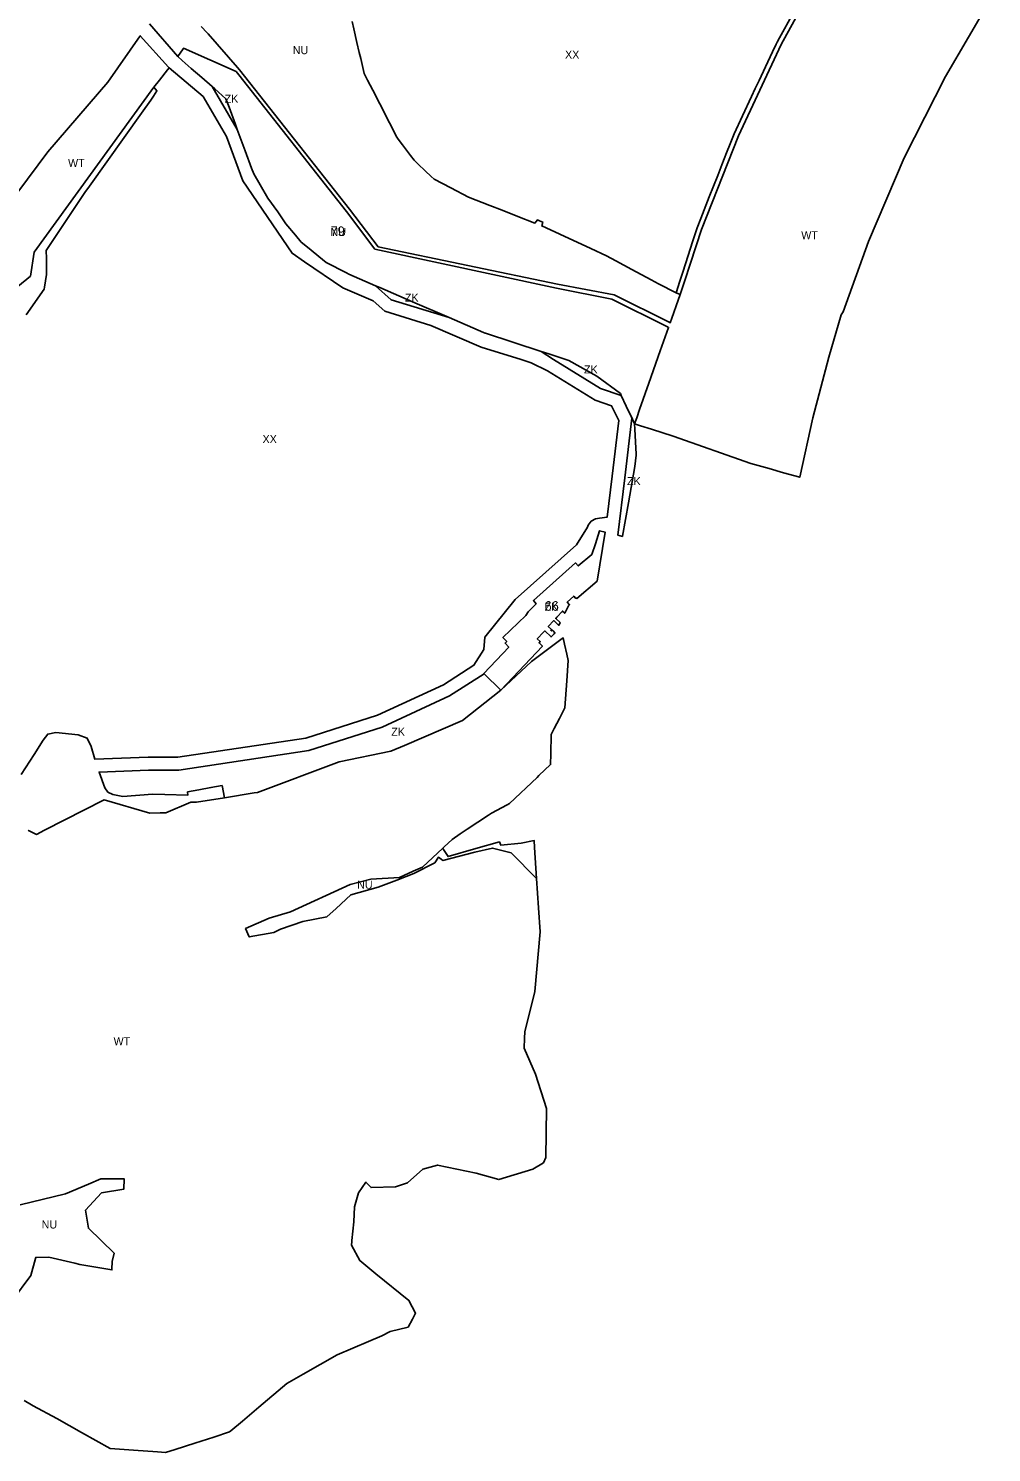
# Model space of a CAD drawing. Extents: x -537068 to -534056, y -1176840 to -1172401.
# Drawn here: x -535534 to -534932, y -1176840 to -1175951 of the extents above; entities that cross this region are included whole.
import ezdxf

# ---------------------------------------------------------------- set-up
doc = ezdxf.new("R2010")
doc.units = 0
for name, color, linetype in [('90550013', 7, 'Continuous'), ('90640013', 7, 'Continuous'), ('90710013', 7, 'Continuous'), ('90710023', 7, 'Continuous'), ('90730013', 7, 'Continuous'), ('90730023', 7, 'Continuous'), ('ID_navrh', 7, 'Continuous')]:
    doc.layers.add(name, color=color, linetype=linetype)

msp = doc.modelspace()

# ---------------------------------------------------------------- linework, layer by layer
at = {"layer": '90550013'}
for points in [[(-535055.84, -1175941.16), (-535064.33, -1175956.65), (-535065.83, -1175959.38), (-535066.01, -1175959.75), (-535066.44, -1175960.66), (-535068.64, -1175965.35), (-535073.02, -1175974.66), (-535077.11, -1175983.38), (-535079.45, -1175988.36), (-535081.8, -1175993.37), (-535087.42, -1176005.32), (-535092.73, -1176016.62), (-535095.2, -1176022.89), (-535097.4, -1176028.49), (-535100.38, -1176036.06), (-535102.94, -1176042.57), (-535105.58, -1176049.27), (-535108.19, -1176055.91), (-535113.55, -1176069.53), (-535115.85, -1176075.39), (-535118.68, -1176084.13), (-535121.45, -1176092.69), (-535124.8, -1176103.02), (-535126.61, -1176108.62), (-535128.98, -1176115.95), (-535139.88, -1176110.34), (-535144.42, -1176107.88), (-535156.56, -1176101.32), (-535166.59, -1176095.9), (-535172.35, -1176092.79), (-535182.15, -1176088.27), (-535201.51, -1176079.34), (-535210.2, -1176075.34), (-535212.9, -1176074.1), (-535212.25, -1176071.68), (-535214.34, -1176070.85), (-535215.59, -1176070.35), (-535217.14, -1176072.33), (-535227.84, -1176068.14), (-535237.65, -1176064.31), (-535245.33, -1176061.3), (-535258.67, -1176056.08), (-535269.7, -1176050.34), (-535280.18, -1176044.88), (-535281.9, -1176043.26), (-535285.76, -1176039.61), (-535290.15, -1176035.46), (-535292.63, -1176033.12), (-535294.94, -1176030.03), (-535299.8, -1176023.52), (-535302.51, -1176019.89), (-535303.44, -1176018.64), (-535304.61, -1176016.37), (-535306.6, -1176012.48), (-535309.37, -1176007.08), (-535311.4, -1176003.13), (-535314.15, -1175997.77), (-535318.46, -1175989.39), (-535321.72, -1175983.04), (-535323.82, -1175978.94), (-535325.11, -1175973.34), (-535326.01, -1175969.46), (-535326.87, -1175965.76), (-535328.33, -1175959.48), (-535330.29, -1175951), (-535331.33, -1175946.51)], [(-535534.97, -1176129.73), (-535523.9, -1176113.7), (-535523.65, -1176112.33), (-535522.26, -1176104.52), (-535522.4, -1176094.37), (-535522.46, -1176089.49), (-535498.36, -1176053.32), (-535495.52, -1176049.34), (-535462.94, -1176003.66), (-535457.15, -1175995.54), (-535455.51, -1175993.05), (-535453.36, -1175989.8), (-535455.23, -1175987.51), (-535451.76, -1175983.06), (-535446.65, -1175976.52), (-535445.68, -1175975.28), (-535424.54, -1175993.21), (-535409.82, -1176018.17), (-535399.63, -1176045.97), (-535368.9, -1176091.15), (-535361.09, -1176096.62), (-535337.12, -1176112.77), (-535318.31, -1176120.82), (-535310.89, -1176127.38), (-535282.17, -1176136.28), (-535250.78, -1176149.88), (-535225.72, -1176157.63), (-535219.59, -1176159.68), (-535209.28, -1176164.66), (-535179.48, -1176182.91), (-535169.19, -1176186.4), (-535164.8, -1176195.6), (-535168.88, -1176230.42), (-535172.06, -1176256.14), (-535176.74, -1176256.58), (-535179.27, -1176256.99), (-535181.94, -1176258.5), (-535183.88, -1176260.97), (-535184.38, -1176262.21), (-535191.15, -1176273.27), (-535229.41, -1176307.51), (-535248.48, -1176331.01), (-535249.03, -1176338.8), (-535255.23, -1176348.54), (-535274.29, -1176360.72), (-535315.47, -1176379.78), (-535360.25, -1176394.06), (-535440.34, -1176406), (-535458.72, -1176406), (-535492.23, -1176407.19), (-535494.36, -1176399.33), (-535496.85, -1176394.02), (-535502.56, -1176391.94), (-535516.43, -1176390.57), (-535521.55, -1176391.5), (-535524.51, -1176395.44), (-535530.06, -1176404.25), (-535538.13, -1176416.77)]]:
    msp.add_lwpolyline(points, dxfattribs=at)
at = {"layer": '90640013'}
for points in [[(-535425.64, -1175949.46), (-535421.93, -1175953.47), (-535421.33, -1175954.12), (-535402.94, -1175975.2), (-535401.83, -1175976.6), (-535332.94, -1176063.63), (-535315.13, -1176087.1), (-535203.12, -1176110.45), (-535167.7, -1176117.17), (-535133.32, -1176134.27), (-535132.61, -1176134.62), (-535131.63, -1176131.83), (-535127.65, -1176120.53), (-535126.42, -1176117.04), (-535123.51, -1176108.22), (-535112.98, -1176076.3), (-535089.97, -1176017.76), (-535063.2, -1175960.77), (-535033.24, -1175906.1)], [(-534931.82, -1175931.47), (-534960.54, -1175980.81), (-534986.37, -1176031.62), (-535008.76, -1176083.79), (-535024.61, -1176127.82), (-535025.82, -1176129.74), (-535033.52, -1176156.02), (-535043.53, -1176194.1), (-535051.68, -1176231.16), (-535061.71, -1176228.3), (-535070.7, -1176225.74), (-535082.15, -1176222.47), (-535130.73, -1176205.55), (-535144.25, -1176201.17), (-535151.07, -1176198.96), (-535154.82, -1176197.75), (-535153.49, -1176193.96), (-535151.7, -1176188.89), (-535145.91, -1176172.43), (-535138.79, -1176152.2), (-535133.61, -1176137.48), (-535134.66, -1176136.96), (-535169.04, -1176119.86), (-535203.59, -1176112.91), (-535317.12, -1176088.61), (-535334.93, -1176065.14), (-535402.23, -1175979.7), (-535403.85, -1175977.64), (-535436.69, -1175963.12), (-535436.86, -1175963.37), (-535437.02, -1175963.6), (-535440.26, -1175968.33), (-535457.98, -1175947.84)], [(-535533.71, -1176451.64), (-535533.49, -1176451.75), (-535528.65, -1176454.2), (-535523.63, -1176451.66), (-535486.24, -1176432.72), (-535457.69, -1176441.02), (-535451.28, -1176440.64), (-535447.75, -1176440.73), (-535432.24, -1176433.99), (-535428.71, -1176434.07), (-535411.14, -1176431.27), (-535392.59, -1176428.31), (-535390.42, -1176427.96), (-535339.41, -1176408.87), (-535307.24, -1176402.28), (-535298.7, -1176398.63), (-535262.36, -1176383.13), (-535238.41, -1176364.03), (-535219.26, -1176346.29), (-535200.88, -1176332.56), (-535199.44, -1176331.49), (-535198.61, -1176335.33), (-535197.26, -1176341.53), (-535196.38, -1176345.61), (-535197.28, -1176358.28), (-535198.48, -1176375.15), (-535201.88, -1176381.84), (-535205.08, -1176388.14), (-535206.96, -1176391.84), (-535207.19, -1176403.93), (-535207.32, -1176410.61), (-535214.63, -1176417.52), (-535215.74, -1176418.57), (-535232.97, -1176434.86), (-535234.57, -1176435.74), (-535244.18, -1176441.03), (-535246.07, -1176442.27), (-535259.38, -1176450.99), (-535263.89, -1176453.95), (-535268.77, -1176457.43), (-535273.76, -1176462.03), (-535274.65, -1176462.84), (-535287.44, -1176474.62), (-535293.14, -1176477.21), (-535301.82, -1176481.16), (-535319.57, -1176482.1), (-535332.49, -1176485.54), (-535369.95, -1176502.58), (-535383.1, -1176506.55), (-535397.91, -1176513.07), (-535395.69, -1176518.21), (-535380.34, -1176515.47), (-535376.22, -1176513.36), (-535362.19, -1176508.54), (-535347.18, -1176505.79), (-535341.33, -1176500.46), (-535332.11, -1176492.04), (-535315, -1176487.27), (-535303.38, -1176482.75), (-535292.89, -1176478.68), (-535279.66, -1176471.94), (-535277.47, -1176468.51), (-535275.78, -1176469.69), (-535274.71, -1176470.43), (-535254.68, -1176465.39), (-535243.6, -1176462.73), (-535231.98, -1176465.74), (-535216.08, -1176481.68), (-535214.91, -1176500.06), (-535213.95, -1176515.16), (-535217.22, -1176552.4), (-535223.43, -1176577.55), (-535223.63, -1176581.58), (-535223.93, -1176587.8), (-535216.72, -1176603.99), (-535209.82, -1176625.43), (-535210.4, -1176656.13), (-535211.81, -1176659.3), (-535218.36, -1176663.32), (-535239.7, -1176669.83), (-535253.79, -1176665.86), (-535277.94, -1176660.78), (-535287.21, -1176663.4), (-535296.79, -1176671.9), (-535304.16, -1176674.29), (-535319.53, -1176674.86), (-535322.75, -1176671.4), (-535327.36, -1176678.19), (-535329.8, -1176686.93), (-535330.38, -1176696.29), (-535331.55, -1176707.87), (-535331.62, -1176708.58), (-535331.85, -1176710.83), (-535326.51, -1176720.46), (-535316.52, -1176728.73), (-535295.86, -1176745.33), (-535291.71, -1176753.33), (-535293.7, -1176757.08), (-535296.36, -1176762.09), (-535307.57, -1176764.65), (-535312.79, -1176767.34), (-535321.04, -1176770.89), (-535340.64, -1176779.33), (-535361.87, -1176791.41), (-535372.13, -1176797.24), (-535389.7, -1176812.08), (-535399.88, -1176820.68), (-535407.1, -1176826.78), (-535407.91, -1176827.46), (-535417.88, -1176830.67), (-535429.63, -1176834.45), (-535441.88, -1176838.39), (-535447.92, -1176840.33), (-535452.94, -1176839.95), (-535468.04, -1176838.81), (-535482.5, -1176837.72), (-535500.42, -1176827.8), (-535515.98, -1176819.18), (-535530.62, -1176811.07), (-535531.67, -1176810.49), (-535536.29, -1176807.93)], [(-535543.5, -1176745.17), (-535532.18, -1176729.85), (-535529.17, -1176719.06), (-535529.02, -1176718.5), (-535520.93, -1176718.34), (-535504.72, -1176722), (-535501.5, -1176722.89), (-535481.43, -1176726.23), (-535481.42, -1176725.84), (-535481.31, -1176720.98), (-535480.13, -1176715.73), (-535496.15, -1176700.28), (-535497.89, -1176689.03), (-535487.93, -1176678.11), (-535474.03, -1176675.92), (-535473.85, -1176669.28), (-535488.35, -1176669.33), (-535496.14, -1176672.63), (-535510.43, -1176678.69), (-535538.74, -1176685.61)]]:
    msp.add_lwpolyline(points, dxfattribs=at)
msp.add_lwpolyline([(-535455.23, -1175987.51), (-535530.06, -1176090.53), (-535532.28, -1176105.42), (-535540.24, -1176112.01), (-535545.43, -1176110.93), (-535546.85, -1176113.06), (-535547.96, -1176114.72), (-535572.04, -1176096.44), (-535570.1, -1176093.95), (-535548.55, -1176064.33), (-535540.25, -1176053.13), (-535521.49, -1176027.83), (-535483.92, -1175984.25), (-535463.75, -1175955.3), (-535446.09, -1175974.93), (-535445.68, -1175975.28), (-535446.65, -1175976.52), (-535451.76, -1175983.06)], close=True, dxfattribs=at)
at = {"layer": '90710013'}
for points in [[(-535418.91, -1175987.01), (-535417.16, -1175988.54), (-535410.18, -1175994.65), (-535408.25, -1175999.88), (-535404.21, -1176010.83), (-535403.12, -1176013.79)], [(-535270.7, -1176131.4), (-535306.88, -1176120.25), (-535316.8, -1176111.47), (-535314.01, -1176112.68), (-535293.74, -1176121.44), (-535272.14, -1176130.78)], [(-535163.15, -1176180), (-535176.06, -1176175.63), (-535205.44, -1176157.63), (-535213.22, -1176152.56), (-535208.54, -1176154.09), (-535196.01, -1176158.19), (-535178.52, -1176168.01), (-535163.75, -1176178.72)], [(-535165.39, -1176267.37), (-535160.94, -1176231.38), (-535156.59, -1176194.24), (-535157.31, -1176192.45), (-535156.89, -1176193.35), (-535154.82, -1176197.75), (-535154.64, -1176200.98), (-535154.2, -1176209.08), (-535153.78, -1176216.75), (-535153.85, -1176217.34), (-535154.71, -1176224.3), (-535158.68, -1176247.16), (-535162.33, -1176267.82), (-535162.42, -1176268.1)], [(-535411.14, -1176431.27), (-535412.61, -1176423.72), (-535419.56, -1176425.01), (-535427.1, -1176426.4), (-535434.13, -1176427.7), (-535433.95, -1176429.62), (-535448.49, -1176429.32), (-535456.08, -1176429.16), (-535474.65, -1176430.44), (-535476.78, -1176430.03), (-535480.98, -1176429.21), (-535483.96, -1176427.79), (-535485.87, -1176425.04), (-535489.51, -1176415.24), (-535458.56, -1176414), (-535439.75, -1176414), (-535358.44, -1176401.88), (-535312.56, -1176387.25), (-535270.44, -1176367.75), (-535248.77, -1176353.91), (-535238.41, -1176364.03), (-535262.36, -1176383.13), (-535298.7, -1176398.63), (-535307.24, -1176402.28), (-535339.41, -1176408.87), (-535390.42, -1176427.96), (-535392.59, -1176428.31)]]:
    msp.add_lwpolyline(points, close=True, dxfattribs=at)
at = {"layer": '90710023'}
msp.add_lwpolyline([(-535178.34, -1176296.11), (-535190.94, -1176306.89), (-535191.27, -1176306.54), (-535191.55, -1176306.8), (-535192.88, -1176305.39), (-535196.99, -1176309.23), (-535195.45, -1176310.76), (-535196.19, -1176311.39), (-535198.46, -1176316.05), (-535199.98, -1176314.7), (-535203.41, -1176318.45), (-535204.15, -1176319.41), (-535201.38, -1176321.9), (-535202.24, -1176323.62), (-535202.93, -1176322.83), (-535205.38, -1176320.67), (-535208.78, -1176324.43), (-535206.8, -1176326.22), (-535207.27, -1176326.74), (-535206.82, -1176327.14), (-535206.35, -1176326.62), (-535205.83, -1176327.09), (-535204.6, -1176328.27), (-535205.13, -1176328.84), (-535207.02, -1176330.88), (-535211.04, -1176327.08), (-535211.77, -1176327.8), (-535215.69, -1176332), (-535213.78, -1176333.79), (-535214.58, -1176334.63), (-535212.46, -1176336.63), (-535238.41, -1176364.03), (-535248.77, -1176353.91), (-535249.05, -1176353.64), (-535233.47, -1176337.17), (-535235.74, -1176334.73), (-535234.76, -1176333.79), (-535237.17, -1176331.26), (-535222.74, -1176317.47), (-535221.32, -1176315.27), (-535216.38, -1176310.11), (-535218.13, -1176308.14), (-535191.79, -1176284.58), (-535190.07, -1176286.5), (-535181.65, -1176279.3), (-535179.27, -1176272.74), (-535176.74, -1176264.58), (-535173.21, -1176265.45)], close=True, dxfattribs=at)
at = {"layer": '90730013'}
for points in [[(-535331.33, -1175946.51), (-535330.29, -1175951), (-535328.33, -1175959.48), (-535326.87, -1175965.76), (-535326.01, -1175969.46), (-535325.11, -1175973.34), (-535323.82, -1175978.94), (-535321.72, -1175983.04), (-535318.46, -1175989.39), (-535314.15, -1175997.77), (-535311.4, -1176003.13), (-535309.37, -1176007.08), (-535306.6, -1176012.48), (-535304.61, -1176016.37), (-535303.44, -1176018.64), (-535302.51, -1176019.89), (-535299.8, -1176023.52), (-535294.94, -1176030.03), (-535292.63, -1176033.12), (-535290.15, -1176035.46), (-535285.76, -1176039.61), (-535281.9, -1176043.26), (-535280.18, -1176044.88), (-535269.7, -1176050.34), (-535258.67, -1176056.08), (-535245.33, -1176061.3), (-535237.65, -1176064.31), (-535227.84, -1176068.14), (-535217.14, -1176072.33), (-535215.59, -1176070.35), (-535214.34, -1176070.85), (-535212.25, -1176071.68), (-535212.9, -1176074.1), (-535210.2, -1176075.34), (-535201.51, -1176079.34), (-535182.15, -1176088.27), (-535172.35, -1176092.79), (-535166.59, -1176095.9), (-535156.56, -1176101.32), (-535144.42, -1176107.88), (-535139.88, -1176110.34), (-535128.98, -1176115.95), (-535126.42, -1176117.04), (-535127.65, -1176120.53), (-535131.63, -1176131.83), (-535132.61, -1176134.62), (-535133.32, -1176134.27), (-535167.7, -1176117.17), (-535203.12, -1176110.45), (-535315.13, -1176087.1), (-535332.94, -1176063.63), (-535401.83, -1175976.6), (-535402.94, -1175975.2), (-535421.33, -1175954.12), (-535421.93, -1175953.47), (-535425.64, -1175949.46)], [(-535538.74, -1176685.61), (-535510.43, -1176678.69), (-535496.14, -1176672.63), (-535488.35, -1176669.33), (-535473.85, -1176669.28), (-535474.03, -1176675.92), (-535487.93, -1176678.11), (-535497.89, -1176689.03), (-535496.15, -1176700.28), (-535480.13, -1176715.73), (-535481.31, -1176720.98), (-535481.42, -1176725.84), (-535481.43, -1176726.23), (-535501.5, -1176722.89), (-535504.72, -1176722), (-535520.93, -1176718.34), (-535529.02, -1176718.5), (-535529.17, -1176719.06), (-535532.18, -1176729.85), (-535543.5, -1176745.17)]]:
    msp.add_lwpolyline(points, dxfattribs=at)
msp.add_lwpolyline([(-535216.08, -1176481.68), (-535231.98, -1176465.74), (-535243.6, -1176462.73), (-535254.68, -1176465.39), (-535274.71, -1176470.43), (-535275.78, -1176469.69), (-535277.47, -1176468.51), (-535279.66, -1176471.94), (-535292.89, -1176478.68), (-535303.38, -1176482.75), (-535315, -1176487.27), (-535332.11, -1176492.04), (-535341.33, -1176500.46), (-535347.18, -1176505.79), (-535362.19, -1176508.54), (-535376.22, -1176513.36), (-535380.34, -1176515.47), (-535395.69, -1176518.21), (-535397.91, -1176513.07), (-535383.1, -1176506.55), (-535369.95, -1176502.58), (-535332.49, -1176485.54), (-535319.57, -1176482.1), (-535301.82, -1176481.16), (-535293.14, -1176477.21), (-535287.44, -1176474.62), (-535274.65, -1176462.84), (-535274.17, -1176463.62), (-535271.44, -1176468.07), (-535253.98, -1176463.11), (-535239.32, -1176458.95), (-535238.54, -1176460.88), (-535225.8, -1176459.71), (-535217.59, -1176458.09), (-535217.32, -1176462.31)], close=True, dxfattribs=at)
at = {"layer": '90730023'}
msp.add_lwpolyline([(-535163.15, -1176180), (-535163.75, -1176178.72), (-535178.52, -1176168.01), (-535196.01, -1176158.19), (-535208.54, -1176154.09), (-535213.22, -1176152.56), (-535248.07, -1176141.17), (-535248.23, -1176141.12), (-535249.25, -1176140.68), (-535270.7, -1176131.4), (-535272.14, -1176130.78), (-535293.74, -1176121.44), (-535314.01, -1176112.68), (-535316.8, -1176111.47), (-535333.44, -1176104.28), (-535334.8, -1176103.36), (-535347.64, -1176096.92), (-535349.8, -1176095.16), (-535359.23, -1176087.47), (-535363.21, -1176084.23), (-535366.75, -1176079.98), (-535372.8, -1176072.73), (-535377.89, -1176065.42), (-535383.95, -1176056.8), (-535388.88, -1176048.37), (-535392.88, -1176041.53), (-535394.14, -1176038.1), (-535398.17, -1176027.18), (-535403.12, -1176013.79), (-535404.21, -1176010.83), (-535408.25, -1175999.88), (-535410.18, -1175994.65), (-535417.16, -1175988.54), (-535418.91, -1175987.01), (-535425.27, -1175981.45), (-535431.84, -1175975.7), (-535437.53, -1175970.72), (-535440.26, -1175968.33), (-535437.02, -1175963.6), (-535436.86, -1175963.37), (-535436.69, -1175963.12), (-535403.85, -1175977.64), (-535402.23, -1175979.7), (-535334.93, -1176065.14), (-535317.12, -1176088.61), (-535203.59, -1176112.91), (-535169.04, -1176119.86), (-535134.66, -1176136.96), (-535133.61, -1176137.48), (-535138.79, -1176152.2), (-535145.91, -1176172.43), (-535151.7, -1176188.89), (-535153.49, -1176193.96), (-535154.82, -1176197.75), (-535156.89, -1176193.35), (-535157.31, -1176192.45), (-535157.32, -1176192.43), (-535160.02, -1176186.67)], close=True, dxfattribs=at)

# ---------------------------------------------------------------- texts
at = {"layer": '90550013'}
for p in [(-535198.31, -1175969.61), (-535387.34, -1176209.75)]:
    msp.add_text('XX', height=5, rotation=360, dxfattribs=at).set_placement(p)
at = {"layer": '90640013'}
for rotation, p in [(360, (-535508.86, -1176037.26)), (0, (-535050.73, -1176082.43)), (360, (-535480.42, -1176585.91))]:
    msp.add_text('WT', height=5, rotation=rotation, dxfattribs=at).set_placement(p)
at = {"layer": '90710013'}
for rotation, p in [(360, (-535411.02, -1175997.16)), (360, (-535298.39, -1176121.43)), (0, (-535186.46, -1176166.28)), (360, (-535159.58, -1176236.05)), (0, (-535306.92, -1176392.59))]:
    msp.add_text('ZK', height=5, rotation=rotation, dxfattribs=at).set_placement(p)
at = {"layer": '90710023'}
msp.add_text('ZK', height=5, rotation=0, dxfattribs=at).set_placement((-535211.13, -1176314.52))
at = {"layer": '90730013'}
for rotation, p in [(360, (-535368.43, -1175966.83)), (0, (-535328.19, -1176488.15)), (360, (-535525.38, -1176700.39))]:
    msp.add_text('NU', height=5, rotation=rotation, dxfattribs=at).set_placement(p)
at = {"layer": '90730023'}
msp.add_text('NU', height=5, rotation=0, dxfattribs=at).set_placement((-535344.85, -1176080.44))
at = {"layer": 'ID_navrh'}
for s, p in [('79', (-535344.85, -1176080.44)), ('66', (-535211.13, -1176314.52))]:
    msp.add_text(s, height=6, rotation=0, dxfattribs=at).set_placement(p)

doc.saveas('drawing.dxf')
